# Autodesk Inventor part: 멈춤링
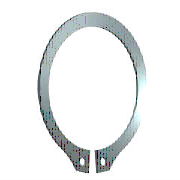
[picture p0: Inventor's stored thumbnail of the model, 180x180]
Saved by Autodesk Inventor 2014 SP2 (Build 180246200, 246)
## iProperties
IsCustomPart: 1
Company: 한국ATC센터
Created: 2014-10
Part Number: 멈춤링
Material: 강, 연강
Description: 리테이닝 링(C형)
Document SubType Name: Modeling
Standard: KS B 1336
Designer: 한국ATC센터
Standards Organization: KS
Language: ko-KR
Size Designation: 25 x 1.2
Categories: <MemberInstance><Categories><Category DisplayName="샤프트 부품" InternalName="7f7aeb1f-a693-4053-b835-cee3144e0d98" Mnemonic="SHFT"><Category DisplayName="써클립" Inter
Density: 7.86 g/cm^3
Mass: 2.3429 g
Surface Area: 7.2498 cm^2
Volume: 0.298079 cm^3
Appearance: 강철
Author: KYOUNG IL JANG
Revision Number: 1
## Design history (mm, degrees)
sketch "스케치1"
  geometry: L1 (-6, 0)-(6, 0) reference; L2 (0, 20.189)-(0, -80.536) reference; L3 (-48.09, 0)-(48.09, 0) reference; L4 (-0.5, -24.44)-(-0.5, -28.74); L5 (-0.5, -6.54)-(-0.5, -13.29); L6 (-2.795, 3.1)-(3.672, 3.1); L7 (0.5, -6.54)-(0.5, -13.29); L8 (0.5, -24.44)-(0.5, -28.74); C1 r 1 at (-2, -26.606); C2 r 1 at (2, -26.606); A1 r 11.95 centre (0, -12.5) between (0.5, -24.44) and (-0.5, -24.44); A2 r 14.825 centre (0, -11.725) between (5.202, -25.608) and (-5.202, -25.608); A3 r 16.247 centre (0, -12.5) between (-2.281, -28.586) and (-0.5, -28.74); A4 r 2 centre (-2, -26.606) between (-3.952, -27.043) and (-2.281, -28.586); A5 r 2 centre (-5.903, -27.48) between (-3.952, -27.043) and (-5.202, -25.608); A6 r 2 centre (5.903, -27.48) between (5.202, -25.608) and (3.952, -27.043); A7 r 2 centre (2, -26.606) between (2.281, -28.586) and (3.952, -27.043); A8 r 16.247 centre (0, -12.5) between (0.5, -28.74) and (2.281, -28.586)
  constraints: 16 point on circle, 12 end point, 10 centre point, 9 symmetric about line, 5 point on line, 4 tangent, 3 coincident, 2 horizontal, 1 perpendicular, 1 vertical, 5 other
  dimensions: "d0" = 23.9 diameter of A1 (= ND); "d1" = 4.3 distance of L4.end L4.start (= SRB2); "d6" = 0.5 distance between parallel lines of L2 L5 (= 0.25 x SD5); "d7" = 3.1 distance between parallel lines of L6 L3 (= SRB1); "d8" = 0.775 distance of A1.centre A2.centre (= 0.25 x SRB1); "d9" = 2 radius of A4 (= SD5); "d10" = 2 radius of A5 (= SD5); "d11" = 1.5 distance from line of L4 A4.centre (= 0.75 x SD5); "d12" = 2 diameter of C1 (= SD5); "d13" = 2 diameter of C2 (= SD5); "d14" = 12.5 distance from line of A1.centre L1 (= 0.5 x WD)
extrude "본체" new body sketch "스케치1" distance "d2" = 1.2 (= SD); taper "d3" = 0 deg
workaxis "Work Axis1"
workplane "Work Plane1"
body "Solid1"
other parameters: "WD" = 25 (= WDMIN) [user parameter; used in 1 equation term], "SD" = 1.2 [user parameter; used in 1 equation term], "SRB1" = 3.1 [user parameter; used in 2 equation terms], "ND" = 23.9 [user parameter; used in 1 equation term], "SRB2" = 4.3 [user parameter; used in 1 equation term], "SD5" = 2 [user parameter; used in 6 equation terms], "d15" = 0, "d16" = 0, "d17" = 0, "d41" = 0, "d42" = 0, "WDMIN" = 25 [user parameter; used in 1 equation term], "SD3" = 23.2 [user parameter], "WDMAX" = 26 [user parameter]
